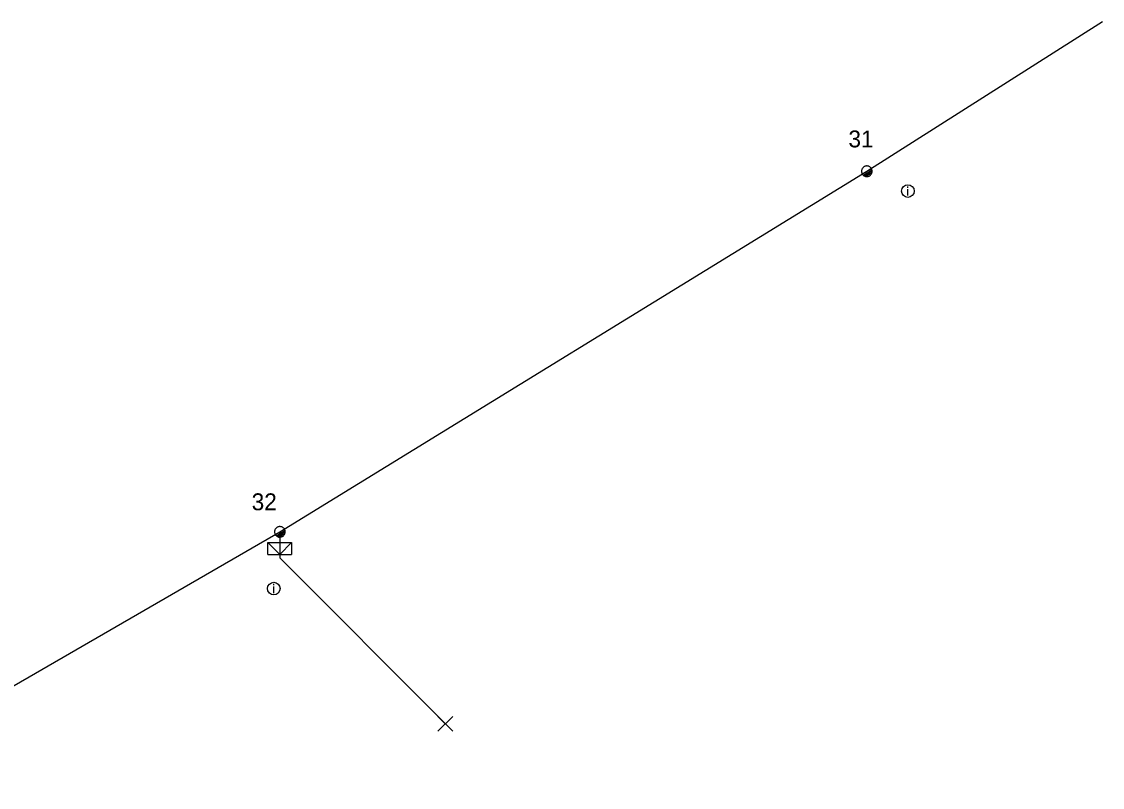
# Model space of a CAD drawing. Extents: x -536149 to -535465, y -1201639 to -1201298.
# Drawn here: x -535529.3 to -535465.3, y -1201539 to -1201493.6 of the extents above; entities that cross this region are included whole.
import ezdxf

# ---------------------------------------------------------------- set-up
doc = ezdxf.new("R2010")
doc.units = 0
for name, color, linetype in [('Vrstva 1', 7, 'Continuous'), ('Vrstva 10', 7, 'Continuous'), ('Vrstva 13', 7, 'Continuous'), ('Vrstva 14', 7, 'Continuous'), ('Vrstva 2', 7, 'Continuous'), ('Vrstva 31', 7, 'Continuous'), ('Vrstva 34', 7, 'Continuous'), ('Vrstva 36', 7, 'Continuous'), ('Vrstva 59', 7, 'Continuous'), ('Vrstva 9', 7, 'Continuous')]:
    doc.layers.add(name, color=color, linetype=linetype)

# ---------------------------------------------------------------- blocks, each defined once
blk = doc.blocks.new('NN440')
at = {"layer": 'Vrstva 2'}
for points in [[(0.63, 0), (0.63, 0.06), (0.62, 0.13), (0.6, 0.19), (0.58, 0.25), (0.55, 0.31), (0.51, 0.37), (0.47, 0.42), (0.42, 0.46), (0.37, 0.51), (0.32, 0.54), (0.26, 0.57), (0.2, 0.59), (0.13, 0.61), (0.07, 0.62), (0, 0.63), (-0.06, 0.62), (-0.13, 0.61), (-0.19, 0.59), (-0.26, 0.57), (-0.31, 0.54), (-0.37, 0.51), (-0.42, 0.46), (-0.47, 0.42), (-0.51, 0.37), (-0.54, 0.31), (-0.57, 0.25), (-0.6, 0.19), (-0.62, 0.13), (-0.63, 0.06), (-0.63, 0), (-0.63, -0.07), (-0.62, -0.14), (-0.6, -0.2), (-0.57, -0.26), (-0.54, -0.32), (-0.51, -0.37), (-0.47, -0.43), (-0.42, -0.47), (-0.37, -0.51), (-0.31, -0.55), (-0.26, -0.58), (-0.19, -0.6), (-0.13, -0.62), (-0.06, -0.63), (0, -0.63), (0.07, -0.63), (0.13, -0.62), (0.2, -0.6), (0.26, -0.58), (0.32, -0.55), (0.37, -0.51), (0.42, -0.47), (0.47, -0.43), (0.51, -0.37), (0.55, -0.32), (0.58, -0.26), (0.6, -0.2), (0.62, -0.14), (0.63, -0.07), (0.63, 0)], [(-0.63, 0), (0.63, 0)], [(-0.6, -0.18), (0.57, -0.18)], [(-0.51, -0.32), (0.5, -0.32)], [(-0.37, -0.47), (0.35, -0.47)]]:
    blk.add_lwpolyline(points, dxfattribs=at)
blk = doc.blocks.new('NN770')
at = {"layer": 'Vrstva 10'}
for p, q in [((0.002, 0.187), (0.002, 0.263)), ((0.002, -0.276), (0.002, 0.111))]:
    blk.add_line(p, q, dxfattribs=at)
blk.add_circle((0, -0.008), 0.375, dxfattribs=at)
blk = doc.blocks.new('NN800')
at = {"layer": 'Vrstva 1'}
for points in [[(-0.442, 0.442), (0.442, -0.442)], [(-0.442, -0.442), (0.442, 0.442)]]:
    blk.add_lwpolyline(points, dxfattribs=at)
blk = doc.blocks.new('NN630')
at = {"layer": 'Vrstva 9'}
for points in [[(-0.003, -0.7), (-0.703, 0)], [(-0.703, -0.7), (-0.703, 0), (0.697, 0), (0.697, -0.7)], [(-0.003, -0.7), (0.697, 0)], [(-0.703, -0.7), (0.697, -0.7)]]:
    blk.add_lwpolyline(points, dxfattribs=at)

msp = doc.modelspace()

# ---------------------------------------------------------------- linework, layer by layer
at = {"layer": 'Vrstva 1'}
msp.add_lwpolyline([(-535540.23, -1201538.98), (-535514.019, -1201523.838), (-535479.236, -1201502.472), (-535465.278, -1201493.607)], dxfattribs=at)
at = {"layer": 'Vrstva 59'}
msp.add_lwpolyline([(-535514.019, -1201523.838), (-535514.019, -1201524.473), (-535514.019, -1201525.386), (-535504.209, -1201535.215)], dxfattribs=at)

# ---------------------------------------------------------------- block references
at = {"layer": 'Vrstva 13', "xscale": 0.5}
for p, yscale, rotation in [((-535479.237, -1201502.473), 0.5000000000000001, 32.42073334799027), ((-535514.018, -1201523.839), 0.5, 31.56097502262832)]:
    msp.add_blockref('NN440', p, dxfattribs=dict(at, yscale=yscale, rotation=rotation))
at = {"layer": 'Vrstva 31'}
msp.add_blockref('NN630', (-535514.019, -1201524.473), dxfattribs=at)
at = {"layer": 'Vrstva 34'}
msp.add_blockref('NN800', (-535504.209, -1201535.215), dxfattribs=at)
at = {"layer": 'Vrstva 36'}
for p in [(-535476.806, -1201503.643), (-535514.375, -1201527.19)]:
    msp.add_blockref('NN770', p, dxfattribs=at)

# ---------------------------------------------------------------- texts
at = {"layer": 'Vrstva 14'}
for s, p in [('31', (-535480.325, -1201501.059)), ('32', (-535515.686, -1201522.559))]:
    msp.add_text(s, height=1, dxfattribs=at).set_placement(p)

doc.saveas('drawing.dxf')
